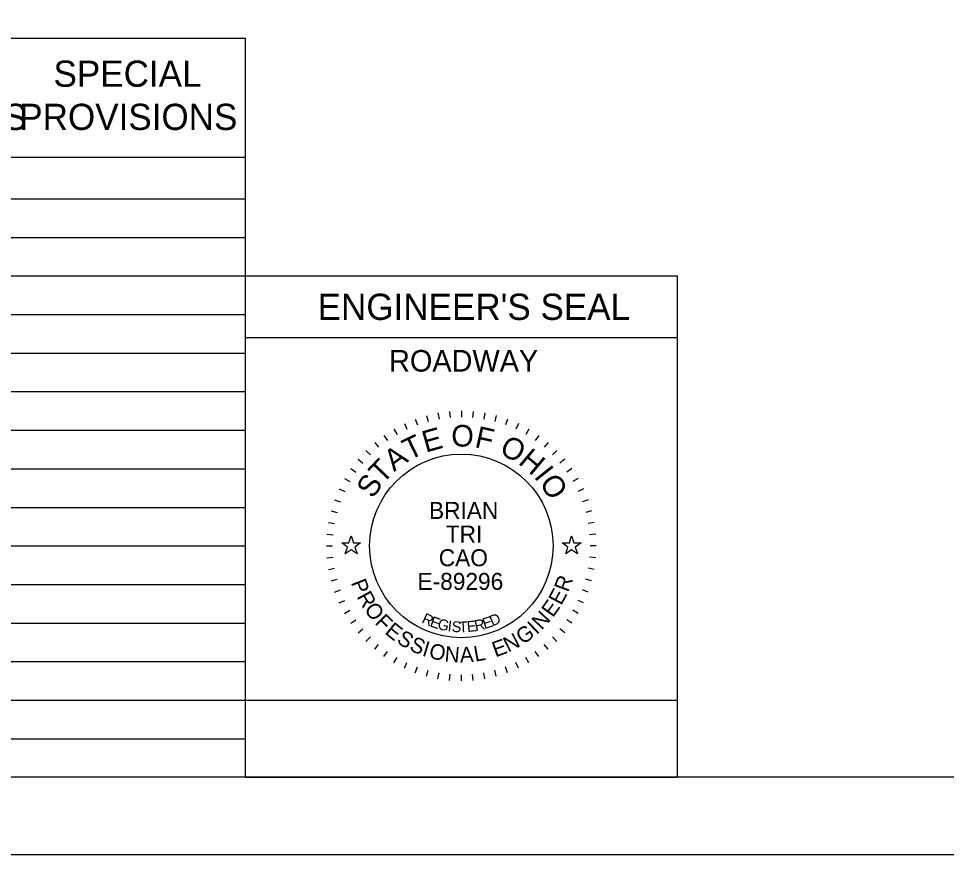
# Model space of a CAD drawing. Extents: x 8.5 to 81.5, y -1.2 to 22.4.
# Drawn here: x 69.65 to 75.67, y 0.35 to 5.77 of the extents above; entities that cross this region are included whole.
import ezdxf

# ---------------------------------------------------------------- set-up
doc = ezdxf.new("R2010")
doc.units = 0
for name, color, linetype in [('Default', 7, 'Continuous'), ('SH_Border', 7, 'Continuous'), ('SH_Cut_Line', 7, 'Continuous'), ('SH_Data', 7, 'Continuous'), ('SH_Text', 7, 'Continuous')]:
    doc.layers.add(name, color=color, linetype=linetype)

msp = doc.modelspace()

# ---------------------------------------------------------------- linework, layer by layer
at = {"layer": 'Default'}
for points in [[(71.7493, 2.3705), (71.7962, 2.3705), (71.8107, 2.4151), (71.8252, 2.3705), (71.8721, 2.3705), (71.8342, 2.3429), (71.8487, 2.2983), (71.8107, 2.3259), (71.7727, 2.2983), (71.7872, 2.3429)], [(73.1793, 2.3705), (73.2262, 2.3705), (73.2407, 2.4151), (73.2552, 2.3705), (73.3021, 2.3705), (73.2642, 2.3429), (73.2787, 2.2983), (73.2407, 2.3259), (73.2027, 2.2983), (73.2172, 2.3429)]]:
    msp.add_lwpolyline(points, close=True, dxfattribs=at)
at = {"layer": 'SH_Border'}
msp.add_lwpolyline([(49.0257, 21.8506), (81.0257, 21.8506), (81.0257, 0.8506), (49.0257, 0.8506)], close=True, dxfattribs=at)
at = {"layer": 'SH_Cut_Line'}
msp.add_lwpolyline([(47.5257, 0.3506), (81.5257, 0.3506), (81.5257, 22.3506), (47.5257, 22.3506)], close=True, dxfattribs=at)
at = {"layer": 'SH_Data'}
for p, q in [((57.6757, 5.6423), (71.1257, 5.6423)), ((71.1257, 0.8506), (71.1257, 5.6423)), ((57.6757, 4.8715), (71.1257, 4.8715)), ((57.6757, 4.6006), (71.1257, 4.6006)), ((57.6757, 4.3506), (71.1257, 4.3506)), ((57.6757, 4.1006), (71.1257, 4.1006)), ((71.1257, 0.8506), (71.1257, 4.1006)), ((71.1257, 4.1006), (73.9257, 4.1006)), ((73.9257, 4.1006), (73.9257, 0.8506)), ((57.6757, 3.8506), (71.1257, 3.8506)), ((71.1257, 3.7006), (73.9257, 3.7006)), ((57.6757, 3.6006), (71.1257, 3.6006)), ((57.6757, 3.3506), (71.1257, 3.3506)), ((72.2992, 3.1957), (72.3096, 3.1571)), ((72.3738, 3.2123), (72.3807, 3.1729)), ((72.4494, 3.2222), (72.4529, 3.1824)), ((72.5257, 3.2256), (72.5257, 3.1856)), ((72.602, 3.2222), (72.5985, 3.1824)), ((72.6776, 3.2123), (72.6707, 3.1729)), ((72.7522, 3.1957), (72.7418, 3.1571)), ((72.1559, 3.1436), (72.1728, 3.1073)), ((72.2264, 3.1728), (72.2401, 3.1352)), ((72.825, 3.1728), (72.8113, 3.1352)), ((72.8955, 3.1436), (72.8786, 3.1073)), ((57.6757, 3.1006), (71.1257, 3.1006)), ((72.0882, 3.1083), (72.1082, 3.0737)), ((72.9632, 3.1083), (72.9432, 3.0737)), ((71.9633, 3.0208), (71.989, 2.9902)), ((72.0238, 3.0673), (72.0468, 3.0345)), ((73.0276, 3.0673), (73.0046, 3.0345)), ((73.0881, 3.0208), (73.0624, 2.9902)), ((71.907, 2.9693), (71.9353, 2.941)), ((73.1444, 2.9693), (73.1161, 2.941)), ((71.8554, 2.913), (71.8861, 2.8873)), ((73.196, 2.913), (73.1654, 2.8873)), ((57.6757, 2.8506), (71.1257, 2.8506)), ((71.8089, 2.8524), (71.8417, 2.8295)), ((73.2425, 2.8524), (73.2097, 2.8295)), ((71.7679, 2.7881), (71.8026, 2.7681)), ((73.2835, 2.7881), (73.2488, 2.7681)), ((71.7327, 2.7203), (71.7689, 2.7034)), ((73.3187, 2.7203), (73.2825, 2.7034)), ((71.7035, 2.6498), (71.7411, 2.6361)), ((73.3479, 2.6498), (73.3104, 2.6361)), ((57.6757, 2.6006), (71.1257, 2.6006)), ((71.6805, 2.577), (71.7192, 2.5667)), ((73.3709, 2.577), (73.3323, 2.5667)), ((71.664, 2.5025), (71.7034, 2.4955)), ((73.3874, 2.5025), (73.348, 2.4955)), ((71.654, 2.4268), (71.6939, 2.4233)), ((73.3974, 2.4268), (73.3575, 2.4233)), ((57.6757, 2.3506), (71.1257, 2.3506)), ((71.6507, 2.3506), (71.6907, 2.3506)), ((73.4007, 2.3506), (73.3607, 2.3506)), ((71.654, 2.2743), (71.6939, 2.2778)), ((73.3974, 2.2743), (73.3575, 2.2778)), ((71.664, 2.1986), (71.7034, 2.2056)), ((73.3874, 2.1986), (73.348, 2.2056)), ((71.6805, 2.1241), (71.7192, 2.1344)), ((73.3709, 2.1241), (73.3323, 2.1344)), ((57.6757, 2.1006), (71.1257, 2.1006)), ((71.7035, 2.0513), (71.7411, 2.065)), ((73.3479, 2.0513), (73.3104, 2.065)), ((71.7327, 1.9808), (71.7689, 1.9977)), ((73.3187, 1.9808), (73.2825, 1.9977)), ((71.7679, 1.9131), (71.8026, 1.9331)), ((73.2835, 1.9131), (73.2488, 1.9331)), ((71.8089, 1.8487), (71.8417, 1.8716)), ((73.2425, 1.8487), (73.2097, 1.8716)), ((57.6757, 1.8506), (71.1257, 1.8506)), ((71.8554, 1.7881), (71.8861, 1.8138)), ((73.196, 1.7881), (73.1654, 1.8138)), ((71.907, 1.7318), (71.9353, 1.7601)), ((73.1444, 1.7318), (73.1161, 1.7601)), ((71.9633, 1.6803), (71.989, 1.7109)), ((73.0881, 1.6803), (73.0624, 1.7109)), ((72.0238, 1.6338), (72.0468, 1.6666)), ((72.0882, 1.5928), (72.1082, 1.6274)), ((72.9632, 1.5928), (72.9432, 1.6274)), ((73.0276, 1.6338), (73.0046, 1.6666)), ((57.6757, 1.6006), (71.1257, 1.6006)), ((72.1559, 1.5575), (72.1728, 1.5938)), ((72.2264, 1.5283), (72.2401, 1.5659)), ((72.825, 1.5283), (72.8113, 1.5659)), ((72.8955, 1.5575), (72.8786, 1.5938)), ((72.2992, 1.5054), (72.3096, 1.544)), ((72.3738, 1.4888), (72.3807, 1.5282)), ((72.4494, 1.4789), (72.4529, 1.5187)), ((72.5257, 1.4756), (72.5257, 1.5156)), ((72.602, 1.4789), (72.5985, 1.5187)), ((72.6776, 1.4888), (72.6707, 1.5282)), ((72.7522, 1.5054), (72.7418, 1.544)), ((57.6757, 1.3506), (71.1257, 1.3506)), ((57.6757, 1.1006), (71.1257, 1.1006)), ((71.1257, 0.8506), (73.9257, 0.8506))]:
    msp.add_line(p, q, dxfattribs=at)
msp.add_lwpolyline([(71.1257, 0.8506), (71.1257, 1.3506), (73.9257, 1.3506), (73.9257, 0.8506)], close=True, dxfattribs=at)
msp.add_circle((72.5257, 2.3506), 0.595, dxfattribs=at)

# ---------------------------------------------------------------- texts
for s, height, p in [("ENGINEER'S SEAL", 0.17, (71.5933, 3.8156)), ('ROADWAY', 0.14, (72.0568, 3.4806)), ('BRIAN', 0.11, (72.3159, 2.5255)), ('TRI', 0.11, (72.4245, 2.3722)), ('CAO', 0.11, (72.3792, 2.2189)), ('E-89296', 0.11, (72.2412, 2.0656))]:
    msp.add_text(s, height=height, dxfattribs=at).set_placement(p)
for s, height, rotation, p in [('O', 0.14, 359.78119, (72.4604, 2.9948)), ('T', 0.14, 25.71674, (72.1873, 2.9024)), ('E', 0.14, 15.75706, (72.2941, 2.9544)), ('F', 0.14, 347.43619, (72.6068, 2.9923)), ('O', 0.14, 332.25863, (72.7655, 2.9521)), ('A', 0.14, 36.47472, (72.0891, 2.8287)), ('H', 0.14, 319.91363, (72.8889, 2.8866)), ('T', 0.14, 46.4344, (72.014, 2.747)), ('I', 0.14, 308.36695, (72.9922, 2.7989)), ('S', 0.14, 57.19238, (71.9538, 2.652)), ('O', 0.14, 303.14906, (73.0279, 2.7594)), ('P', 0.1, 291.49398, (71.808, 2.1126)), ('R', 0.1, 69.23216, (73.2176, 2.0459)), ('R', 0.1, 298.73106, (71.8447, 2.0222)), ('E', 0.1, 61.99508, (73.1733, 1.9604)), ('E', 0.1, 54.75801, (73.119, 1.8819)), ('O', 0.1, 306.46664, (71.8912, 1.9388)), ('N', 0.1, 47.02243, (73.0459, 1.8013)), ('F', 0.1, 314.7068, (71.96, 1.8488)), ('R', 0.07, 334.48695, (72.2632, 1.8556)), ('E', 0.07, 341.03996, (72.3163, 1.8306)), ('G', 0.07, 347.47515, (72.3672, 1.8124)), ('I', 0.07, 353.78581, (72.4348, 1.7974)), ('E', 0.07, 6.01169, (72.5647, 1.7918)), ('R', 0.07, 11.91844, (72.6182, 1.7979)), ('E', 0.07, 17.68363, (72.6755, 1.8107)), ('D', 0.07, 23.30524, (72.7267, 1.8276)), ('E', 0.1, 321.43929, (72.0235, 1.7853)), ('S', 0.07, 356.89262, (72.4615, 1.7934)), ('T', 0.07, 3.00609, (72.5114, 1.7892)), ('G', 0.1, 35.04687, (72.9238, 1.7076)), ('I', 0.1, 43.28703, (73.0126, 1.7719)), ('S', 0.1, 328.67637, (72.1, 1.7258)), ('S', 0.1, 335.91345, (72.1821, 1.6771)), ('E', 0.1, 20.07421, (72.7469, 1.6276)), ('N', 0.1, 27.31129, (72.8302, 1.6581)), ('I', 0.1, 343.15053, (72.2663, 1.6402)), ('O', 0.1, 346.88592, (72.3096, 1.6257)), ('N', 0.1, 355.12608, (72.4145, 1.6023)), ('A', 0.1, 2.86166, (72.518, 1.5942)), ('L', 0.1, 10.09874, (72.6151, 1.5996))]:
    msp.add_text(s, height=height, rotation=rotation, dxfattribs=at).set_placement(p)
at = {"layer": 'SH_Text'}
for s, p in [('SPECIAL', (69.8799, 5.3269)), ('SPECIFICATIONS', (67.8128, 5.0469)), ('PROVISIONS', (69.658, 5.0469))]:
    msp.add_text(s, height=0.17, dxfattribs=at).set_placement(p)

doc.saveas('drawing.dxf')
